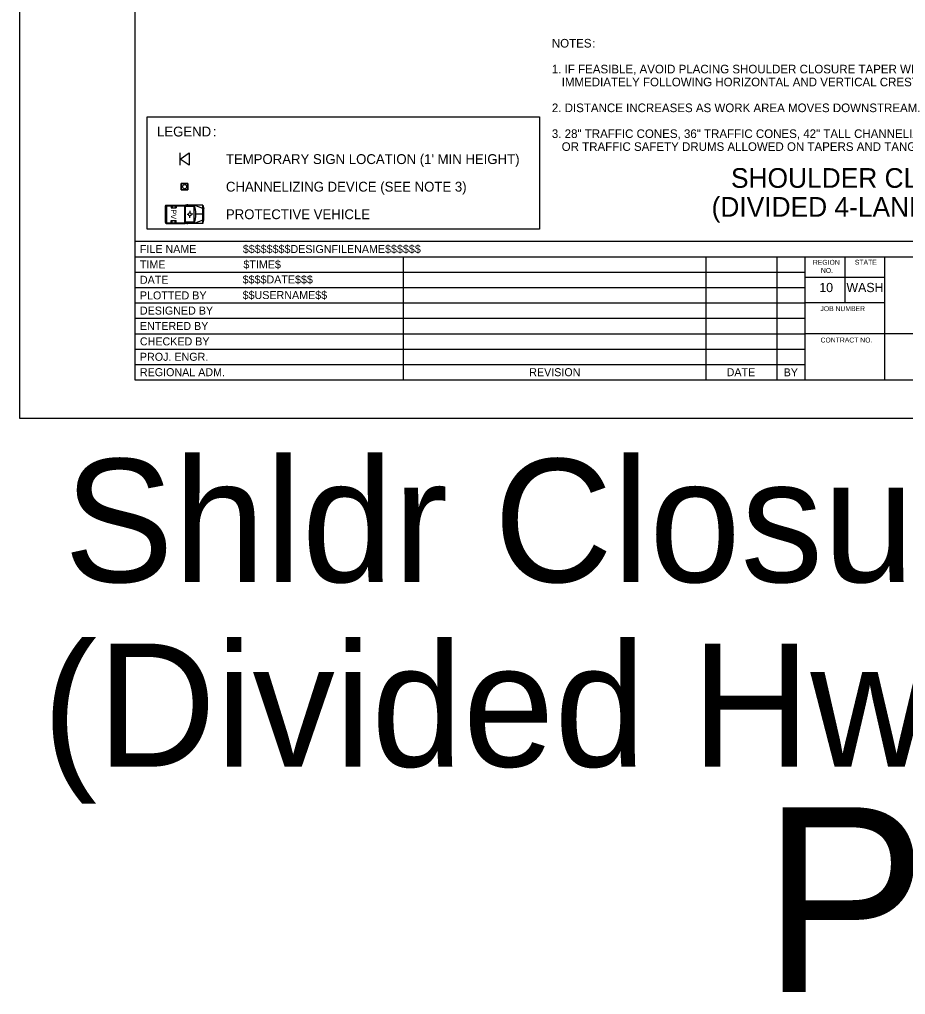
# Model space of a CAD drawing. Extents: x 99999.1 to 100055.7, y 99995 to 100010.7.
# Drawn here: x 100019.06 to 100026.26, y 99995.01 to 100002.93 of the extents above; entities that cross this region are included whole.
import ezdxf

# ---------------------------------------------------------------- set-up
doc = ezdxf.new("R2010")
doc.units = 0
for name, color, linetype in [('SH_DE_DetailHeading1Text', 7, 'Continuous'), ('SH_GI_GeneralNotesBodyText', 7, 'Continuous'), ('SH_GI_PlotLimits', 7, 'Continuous'), ('SH_GI_SheetBorder', 7, 'Continuous'), ('SH_GI_SheetLocationText', 7, 'Continuous'), ('SH_GI_SheetTextInCells', 7, 'Continuous'), ('SH_GI_TitleBlockText', 7, 'Continuous'), ('TR_WZ_PortableSignMountBlk-Wht', 7, 'Continuous'), ('TR_WZ_ProtectiveVehicle', 7, 'Continuous'), ('TR_WZ_TrafficCone', 7, 'Continuous'), ('TR_WZ_WorkZoneTextCurrent', 7, 'Continuous')]:
    doc.layers.add(name, color=color, linetype=linetype)

msp = doc.modelspace()

# ---------------------------------------------------------------- linework, layer by layer
at = {"layer": 'SH_GI_PlotLimits'}
msp.add_lwpolyline([(100019.0625, 99999.6875), (100036.0625, 99999.6875), (100036.0625, 100010.6875), (100019.0625, 100010.6875)], close=True, dxfattribs=at)
at = {"layer": 'SH_GI_SheetBorder'}
for p, q in [((100020, 100010.375), (100020, 100000)), ((100020, 100001.1259), (100035.75, 100001.1259)), ((100020, 100001.0008), (100027.4566, 100001.0008)), ((100022.179, 100001.0008), (100022.179, 100000)), ((100024.641, 100001.0008), (100024.641, 100000)), ((100025.2164, 100001.0008), (100025.2164, 100000)), ((100025.4451, 100001.0008), (100025.4451, 100000)), ((100025.7719, 100000.6255), (100025.7719, 100001.0008)), ((100026.0956, 100000), (100026.0956, 100001.0008)), ((100020, 100000.8757), (100022.1821, 100000.8757)), ((100022.1821, 100000.8757), (100025.4466, 100000.8757)), ((100026.0958, 100000.831), (100025.4466, 100000.831)), ((100020, 100000.7506), (100022.1821, 100000.7506)), ((100022.1821, 100000.7506), (100025.4466, 100000.7506)), ((100020, 100000.6255), (100025.4466, 100000.6255)), ((100026.0958, 100000.6255), (100025.4466, 100000.6255)), ((100020, 100000.5004), (100025.4466, 100000.5004)), ((100020, 100000.3753), (100025.4466, 100000.3753)), ((100027.4566, 100000.3753), (100025.4466, 100000.3753)), ((100020, 100000.2502), (100025.4466, 100000.2502)), ((100020, 100000.1251), (100025.4466, 100000.1251)), ((100020, 100000), (100035.75, 100000))]:
    msp.add_line(p, q, dxfattribs=at)
at = {"layer": 'TR_WZ_PortableSignMountBlk-Wht'}
msp.add_line((100020.3682, 100001.7439), (100020.3682, 100001.8439), dxfattribs=at)
msp.add_lwpolyline([(100020.3682, 100001.7938), (100020.44, 100001.8439), (100020.44, 100001.7439)], close=True, dxfattribs=at)
at = {"layer": 'TR_WZ_ProtectiveVehicle'}
for p, q in [((100020.248, 100001.2779), (100020.248, 100001.4138)), ((100020.2514, 100001.4184), (100020.2547, 100001.4184)), ((100020.2547, 100001.2733), (100020.2547, 100001.4184)), ((100020.2552, 100001.4208), (100020.4095, 100001.4208)), ((100020.2552, 100001.2708), (100020.2552, 100001.4208)), ((100020.2596, 100001.2768), (100020.2596, 100001.4149)), ((100020.2596, 100001.4149), (100020.4052, 100001.4149)), ((100020.2944, 100001.4149), (100020.2944, 100001.3976)), ((100020.2944, 100001.3976), (100020.3356, 100001.3976)), ((100020.3026, 100001.4149), (100020.3026, 100001.3976)), ((100020.3281, 100001.4149), (100020.3281, 100001.3976)), ((100020.3356, 100001.4149), (100020.3356, 100001.3976)), ((100020.4052, 100001.2768), (100020.4052, 100001.4149)), ((100020.4095, 100001.2708), (100020.4095, 100001.4208)), ((100020.4116, 100001.2708), (100020.4116, 100001.4208)), ((100020.5533, 100001.4208), (100020.4116, 100001.4208)), ((100020.4811, 100001.4092), (100020.4116, 100001.4092)), ((100020.4309, 100001.423), (100020.4224, 100001.423)), ((100020.4737, 100001.4092), (100020.4811, 100001.4208)), ((100020.4811, 100001.2708), (100020.4811, 100001.4208)), ((100020.4824, 100001.2708), (100020.4824, 100001.4208)), ((100020.5533, 100001.3934), (100020.4824, 100001.4208)), ((100020.5533, 100001.2708), (100020.5533, 100001.4208)), ((100020.5533, 100001.4208), (100020.5602, 100001.3906)), ((100020.5602, 100001.3011), (100020.5602, 100001.3906)), ((100020.248, 100001.3564), (100020.2547, 100001.3536)), ((100020.248, 100001.3353), (100020.2547, 100001.3381)), ((100020.2498, 100001.3458), (100020.2529, 100001.3458)), ((100020.2514, 100001.3437), (100020.2514, 100001.348)), ((100020.424, 100001.3464), (100020.4352, 100001.3461)), ((100020.4366, 100001.3461), (100020.4366, 100001.3461)), ((100020.4466, 100001.3747), (100020.4468, 100001.3634)), ((100020.4471, 100001.3161), (100020.4471, 100001.3282)), ((100020.4698, 100001.3457), (100020.4603, 100001.3458)), ((100020.5533, 100001.3458), (100020.4963, 100001.3458)), ((100020.5533, 100001.2708), (100020.5602, 100001.3011)), ((100020.2514, 100001.2733), (100020.2547, 100001.2733)), ((100020.2552, 100001.2708), (100020.4095, 100001.2708)), ((100020.2596, 100001.2768), (100020.4052, 100001.2768)), ((100020.2944, 100001.2941), (100020.3356, 100001.2941)), ((100020.2944, 100001.2768), (100020.2944, 100001.2941)), ((100020.3026, 100001.2768), (100020.3026, 100001.2941)), ((100020.3281, 100001.2768), (100020.3281, 100001.2941)), ((100020.3356, 100001.2768), (100020.3356, 100001.2941)), ((100020.4811, 100001.2825), (100020.4116, 100001.2825)), ((100020.5533, 100001.2708), (100020.4116, 100001.2708)), ((100020.4309, 100001.2687), (100020.4224, 100001.2687)), ((100020.4811, 100001.2708), (100020.4721, 100001.2825)), ((100020.5533, 100001.2983), (100020.4824, 100001.2708))]:
    msp.add_line(p, q, dxfattribs=at)
for centre, major_axis, start_param, end_param in [((100020.2514, 100001.4138), (0, 0.00458), 0, 1.570796), ((100020.3812, 100001.3459), (0, 0.1574), 4.215667, 5.208926), ((100020.2514, 100001.2779), (0, -0.00458), 4.712389, 6.283185)]:
    msp.add_ellipse(centre, major_axis=major_axis, ratio=0.73155, start_param=start_param, end_param=end_param, dxfattribs=at)
for centre, major_axis in [((100020.2514, 100001.3458), (0, -0.00211)), ((100020.4471, 100001.3458), (0, -0.0144))]:
    msp.add_ellipse(centre, major_axis=major_axis, ratio=0.73155, dxfattribs=at)
at = {"layer": 'TR_WZ_TrafficCone'}
for points in [[(100020.4308, 100001.5966), (100020.4308, 100001.5432), (100020.3775, 100001.5432), (100020.3775, 100001.5966), (100020.4308, 100001.5966)], [(100020.3775, 100001.5966), (100020.3775, 100001.5432), (100020.4308, 100001.5432), (100020.4308, 100001.5966), (100020.3775, 100001.5966)]]:
    msp.add_lwpolyline(points, dxfattribs=at)
msp.add_circle((100020.4041, 100001.5699), 0.0167, dxfattribs=at)
at = {"layer": 'TR_WZ_WorkZoneTextCurrent'}
msp.add_lwpolyline([(100020.1, 100002.1379), (100023.2886, 100002.1379), (100023.2886, 100001.2259), (100020.1, 100001.2259)], close=True, dxfattribs=at)

# ---------------------------------------------------------------- texts
at = {"layer": 'SH_DE_DetailHeading1Text'}
for s, p in [('SHOULDER CLOSURE WITH ENCROACHMENT', (100024.8442, 100001.5606)), ('(DIVIDED 4-LANE HIGHWAYS, 40 MPH OR LESS)', (100024.6868, 100001.3259))]:
    msp.add_text(s, height=0.16, rotation=360, dxfattribs=at).set_placement(p)
at = {"layer": 'SH_GI_GeneralNotesBodyText'}
for s, p in [('NOTES', (100023.3886, 100002.7006)), (':', (100023.7161, 100002.7006)), ('1. IF FEASIBLE, AVOID PLACING SHOULDER CLOSURE TAPER WITHIN OR ', (100023.3886, 100002.4906)), ('IMMEDIATELY FOLLOWING HORIZONTAL AND VERTICAL CREST CURVES.', (100023.4686, 100002.3856)), ('2. DISTANCE INCREASES AS WORK AREA MOVES DOWNSTREAM.', (100023.3886, 100002.1756)), ('3. 28" TRAFFIC CONES, 36" TRAFFIC CONES, 42" TALL CHANNELIZING DEVICES, ', (100023.3886, 100001.9656)), ('OR TRAFFIC SAFETY DRUMS ALLOWED ON TAPERS AND TANGENTS.', (100023.4686, 100001.8606))]:
    msp.add_text(s, height=0.07, rotation=360, dxfattribs=at).set_placement(p)
at = {"layer": 'SH_GI_SheetLocationText'}
for s, height, p in [('Shldr Closure + Encroachment', 1, (100019.424, 99998.3571)), ('(Divided Hwy, 40 mph & Less)', 1, (100019.2479, 99996.8571)), ('Plot 2', 1.5, (100025.0998, 99995.0267))]:
    msp.add_text(s, height=height, dxfattribs=at).set_placement(p)
at = {"layer": 'SH_GI_SheetTextInCells'}
for s, height, p in [('FILE NAME', 0.06505, (100020.041, 100001.0308)), ('TIME', 0.06505, (100020.041, 100000.9057)), ('REGION', 0.04003, (100025.5099, 100000.9352)), ('NO.', 0.04003, (100025.5752, 100000.869)), ('STATE', 0.04003, (100025.8511, 100000.9357)), ('DATE', 0.06505, (100020.041, 100000.7806)), ('10', 0.07506, (100025.5621, 100000.7131)), ('WASH', 0.07506, (100025.7826, 100000.7131)), ('PLOTTED BY', 0.06505, (100020.041, 100000.6538)), ('DESIGNED BY', 0.065052, (100020.041, 100000.5304)), ('JOB NUMBER', 0.04003, (100025.5712, 100000.5587)), ('ENTERED BY', 0.06505, (100020.041, 100000.4053)), ('CHECKED BY', 0.06505, (100020.041, 100000.2802)), ('CONTRACT NO.', 0.040032, (100025.5725, 100000.3037)), ('PROJ. ENGR.', 0.065052, (100020.041, 100000.1551)), ('REGIONAL ADM.', 0.065052, (100020.041, 100000.03)), ('REVISION', 0.06505, (100023.2048, 100000.03)), ('DATE', 0.06505, (100024.8091, 100000.03)), ('BY', 0.06505, (100025.2725, 100000.0285))]:
    msp.add_text(s, height=height, dxfattribs=at).set_placement(p)
at = {"layer": 'SH_GI_TitleBlockText'}
for s, height, p in [('$$$$$$$$DESIGNFILENAME$$$$$$', 0.065052, (100020.8775, 100001.0308)), ('$TIME$', 0.06505, (100020.882, 100000.9059)), ('$$$$DATE$$$', 0.065052, (100020.8759, 100000.7835)), ('$$USERNAME$$', 0.065052, (100020.8759, 100000.6567))]:
    msp.add_text(s, height=height, dxfattribs=at).set_placement(p)
at = {"layer": 'TR_WZ_ProtectiveVehicle'}
msp.add_text('PV', height=0.045, rotation=270, dxfattribs=at).set_placement((100020.2925, 100001.3862))
at = {"layer": 'TR_WZ_WorkZoneTextCurrent'}
for s, p in [('LEGEND', (100020.18, 100001.9779)), (':', (100020.6328, 100001.9779)), ("TEMPORARY SIGN LOCATION (1' MIN HEIGHT)", (100020.74, 100001.7539)), ('CHANNELIZING DEVICE (SEE NOTE 3)', (100020.74, 100001.5299)), ('PROTECTIVE VEHICLE', (100020.74, 100001.3059))]:
    msp.add_text(s, height=0.08, rotation=360, dxfattribs=at).set_placement(p)

doc.saveas('drawing.dxf')
